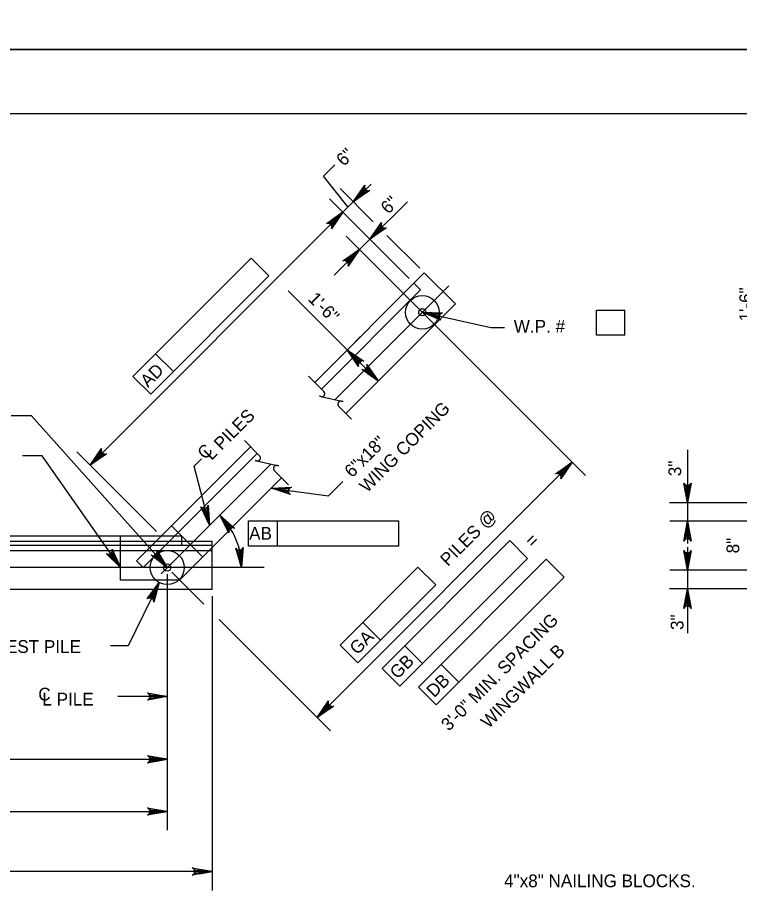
# Model space of a CAD drawing. Extents: x 638304 to 640306, y 296653 to 298435.
# Drawn here: x 638840 to 639009.6, y 297643.6 to 297849 of the extents above; entities that cross this region are included whole.
import ezdxf

# ---------------------------------------------------------------- set-up
doc = ezdxf.new("R2010")
doc.units = 0
for name, color, linetype in [('2', 7, 'Continuous'), ('Level 2', 7, 'Continuous'), ('Level 4', 7, 'Continuous'), ('Level 5', 7, 'Continuous'), ('PLT-BNDY', 7, 'Continuous')]:
    doc.layers.add(name, color=color, linetype=linetype)

msp = doc.modelspace()

# ---------------------------------------------------------------- linework, layer by layer
at = {"layer": '2'}
msp.add_line((638475.46, 297826.46), (639261.46, 297826.46), dxfattribs=at)
at = {"layer": 'Level 2'}
for p, q in [((638909.84, 297763.3), (638935.57, 297789.02)), ((638935.57, 297789.02), (638942.86, 297781.73)), ((638917.14, 297756), (638942.86, 297781.73)), ((638873.77, 297727.22), (638894.76, 297748.22)), ((638878.04, 297716.91), (638902.06, 297740.92)), ((638883.5, 297722.36), (638876.2, 297729.66)), ((638873.77, 297727.22), (638627.67, 297727.22)), ((638864.25, 297716.91), (638864.25, 297727.22)), ((638885.73, 297714.7), (638885.73, 297724.6)), ((638878.04, 297716.91), (638864.25, 297716.91)), ((638885.73, 297714.7), (638616.86, 297714.7))]:
    msp.add_line(p, q, dxfattribs=at)
msp.add_lwpolyline([(638864.25, 297719.86), (638845.84, 297746.05), (638841.24, 297746.05)], dxfattribs=at)
msp.add_lwpolyline([(638864.25, 297719.86), (638862.76, 297722.41), (638862.36, 297722.13)], close=True, dxfattribs=at)
at = {"layer": 'Level 4'}
for p, q in [((638911.41, 297761.73), (638934.7, 297785.02)), ((638933.14, 297786.59), (638934.7, 297785.02)), ((638869.53, 297719.86), (638896.33, 297746.65)), ((638873.77, 297727.22), (638867.97, 297721.42)), ((638878.65, 297727.22), (638873.77, 297727.22)), ((638878.65, 297725.01), (638878.65, 297727.22)), ((638616.86, 297726.08), (638885.73, 297726.08)), ((638885.73, 297724.6), (638885.73, 297726.08)), ((638885.73, 297725.01), (638616.86, 297725.01)), ((638616.86, 297723.87), (638885.73, 297723.87)), ((638869.53, 297719.86), (638867.97, 297721.42))]:
    msp.add_line(p, q, dxfattribs=at)
for points in [[(638935.1, 297779.76), (638951.19, 297776.21), (638954.41, 297776.21)], [(638875.2, 297719.86), (638843.29, 297755.47), (638838.53, 297755.47)], [(638899.66, 297738.52), (638913.04, 297736.69), (638916.4, 297740.04)]]:
    msp.add_lwpolyline(points, dxfattribs=at)
for points in [[(638935.1, 297779.76), (638937.93, 297778.88), (638938.04, 297779.36)], [(638899.66, 297738.52), (638902.54, 297737.88), (638902.61, 297738.36)], [(638875.2, 297719.86), (638873.42, 297722.22), (638873.05, 297721.89)]]:
    msp.add_lwpolyline(points, close=True, dxfattribs=at)
for centre, radius in [((638935.1, 297779.76), 3.93), ((638875.2, 297719.86), 4.01)]:
    msp.add_circle(centre, radius, dxfattribs=at)
at = {"layer": 'Level 5'}
for p, q in [((638911.91, 297811.73), (638914.59, 297814.41)), ((638917.68, 297804.47), (638911.91, 297811.73)), ((638918.9, 297805.69), (638923.06, 297809.86)), ((638923.58, 297801.01), (638915.77, 297808.82)), ((638932.05, 297787.67), (638913.34, 297806.39)), ((638914.03, 297800.83), (638918.9, 297805.69)), ((638922.81, 297796.92), (638931.6, 297805.7)), ((638857.1, 297743.9), (638916.46, 297803.26)), ((638914.38, 297801.18), (638912.3, 297799.09)), ((638932.05, 297787.67), (638919.68, 297800.04)), ((638917.25, 297797.61), (638946.87, 297767.99)), ((638934.48, 297790.1), (638926.79, 297797.8)), ((638922.81, 297796.91), (638920.38, 297794.48)), ((638920.38, 297794.48), (638914.36, 297788.46)), ((638867.14, 297764.71), (638894.93, 297792.49)), ((638894.93, 297792.49), (638899.09, 297788.32)), ((638871.31, 297760.54), (638899.09, 297788.32)), ((638917.48, 297770.93), (638903.59, 297784.82)), ((638914.57, 297759.23), (638941.33, 297785.98)), ((638976.04, 297780.27), (638982.62, 297780.27)), ((638976.04, 297774.37), (638976.04, 297780.27)), ((638982.62, 297774.37), (638982.62, 297780.27)), ((638982.62, 297774.37), (638976.04, 297774.37)), ((638918.08, 297771.53), (638920.6, 297774.06)), ((638924.77, 297763.64), (638917.48, 297770.93)), ((638872.48, 297770.04), (638876.64, 297765.88)), ((638925.37, 297764.24), (638927.9, 297766.76)), ((638946.87, 297767.99), (638973.43, 297741.43)), ((638867.14, 297764.71), (638871.31, 297760.54)), ((638908.4, 297764.74), (638911.99, 297761.16)), ((638915.41, 297757.73), (638918.46, 297754.68)), ((638893.31, 297749.67), (638896.89, 297746.08)), ((638872.69, 297728.31), (638853.98, 297747.02)), ((638997.36, 297747.49), (638997.36, 297730.72)), ((638873.75, 297718.4), (638899.5, 297744.15)), ((638881.49, 297743.61), (638883.22, 297745.34)), ((638885.14, 297729.79), (638881.49, 297743.61)), ((638910.41, 297684.65), (638970.31, 297744.55)), ((638900.32, 297742.66), (638903.71, 297739.26)), ((638872.69, 297728.31), (638860.32, 297740.68)), ((639032.53, 297735.04), (638993.12, 297735.04)), ((638894.26, 297730.8), (638929.49, 297730.8)), ((638894.26, 297724.9), (638894.26, 297730.8)), ((638901.09, 297724.9), (638901.09, 297730.8)), ((638929.49, 297730.8), (638929.49, 297724.9)), ((639059.87, 297730.72), (638993.2, 297730.72)), ((638997.36, 297729.69), (638997.36, 297725.53)), ((638925.64, 297696.17), (638955.65, 297726.18)), ((638955.65, 297726.18), (638959.82, 297722.01)), ((638929.49, 297724.9), (638894.26, 297724.9)), ((638997.36, 297724.61), (638997.36, 297724.22)), ((638997.36, 297724.39), (638997.36, 297714.89)), ((638929.81, 297692.01), (638959.82, 297722.01)), ((638934.2, 297691.79), (638964.21, 297721.8)), ((638964.21, 297721.8), (638968.38, 297717.63)), ((638897.93, 297719.86), (638605.59, 297719.86)), ((638915.77, 297701.65), (638934.08, 297719.96)), ((638934.08, 297719.96), (638938.25, 297715.79)), ((639049.8, 297719.21), (638993.2, 297719.21)), ((638997.36, 297719.21), (638997.36, 297704.46)), ((638875.2, 297718.32), (638875.2, 297658.18)), ((638876.29, 297718.77), (638883.79, 297711.27)), ((638938.37, 297687.63), (638968.38, 297717.63)), ((638873.32, 297716.32), (638866.06, 297701.45)), ((638919.94, 297697.48), (638938.25, 297715.79)), ((639032.53, 297714.89), (638993.12, 297714.89)), ((638885.73, 297713.16), (638885.73, 297644.06)), ((638887.4, 297707.66), (638913.53, 297681.53)), ((638921.11, 297706.99), (638925.28, 297702.82)), ((638866.06, 297701.45), (638861.87, 297701.45)), ((638915.77, 297701.65), (638919.94, 297697.48)), ((638930.98, 297701.51), (638935.15, 297697.34)), ((638939.54, 297697.13), (638943.7, 297692.96)), ((638925.64, 297696.17), (638929.81, 297692.01)), ((638934.2, 297691.79), (638938.37, 297687.63)), ((638875.2, 297689.57), (638863.61, 297689.57)), ((638626.05, 297674.84), (638875.2, 297674.84)), ((638754.75, 297662.6), (638875.2, 297662.6)), ((638885.73, 297648.48), (638616.86, 297648.48))]:
    msp.add_line(p, q, dxfattribs=at)
for points in [[(638918.9, 297805.69), (638921.57, 297809.6), (638921.49, 297809.17), (638921.58, 297808.82), (638921.76, 297808.56), (638922.02, 297808.38), (638922.37, 297808.29), (638922.8, 297808.36), (638918.9, 297805.69), (638922.37, 297808.29), (638922.02, 297808.38), (638918.9, 297805.69), (638921.76, 297808.56), (638921.58, 297808.82), (638918.9, 297805.69), (638921.49, 297809.17)], [(638916.46, 297803.26), (638913.79, 297799.35), (638913.87, 297799.78), (638913.78, 297800.13), (638913.6, 297800.39), (638913.34, 297800.57), (638912.99, 297800.66), (638912.56, 297800.59), (638916.46, 297803.26), (638912.99, 297800.66), (638913.34, 297800.57), (638916.46, 297803.26), (638913.6, 297800.39), (638913.78, 297800.13), (638916.46, 297803.26), (638913.87, 297799.78)], [(638922.81, 297796.92), (638925.48, 297800.82), (638925.41, 297800.39), (638925.5, 297800.04), (638925.68, 297799.78), (638925.94, 297799.6), (638926.29, 297799.51), (638926.72, 297799.59), (638922.81, 297796.92), (638926.29, 297799.51), (638925.94, 297799.6), (638922.81, 297796.92), (638925.68, 297799.78), (638925.5, 297800.04), (638922.81, 297796.92), (638925.41, 297800.39)], [(638920.38, 297794.48), (638917.71, 297790.58), (638917.78, 297791.01), (638917.69, 297791.36), (638917.51, 297791.62), (638917.25, 297791.8), (638916.9, 297791.89), (638916.47, 297791.81), (638920.38, 297794.48), (638916.9, 297791.89), (638917.25, 297791.8), (638920.38, 297794.48), (638917.51, 297791.62), (638917.69, 297791.36), (638920.38, 297794.48), (638917.78, 297791.01)], [(638935.1, 297779.76), (638939.83, 297779.61), (638939.43, 297779.44), (638939.18, 297779.18), (638939.06, 297778.89), (638939.05, 297778.57), (638939.16, 297778.23), (638939.46, 297777.9), (638935.1, 297779.76), (638939.16, 297778.23), (638939.05, 297778.57), (638935.1, 297779.76), (638939.06, 297778.89), (638939.18, 297779.18), (638935.1, 297779.76), (638939.43, 297779.44)], [(638917.48, 297770.93), (638921.38, 297768.26), (638920.96, 297768.34), (638920.6, 297768.25), (638920.34, 297768.07), (638920.16, 297767.81), (638920.07, 297767.46), (638920.15, 297767.03), (638917.48, 297770.93), (638920.07, 297767.46), (638920.16, 297767.81), (638917.48, 297770.93), (638920.34, 297768.07), (638920.6, 297768.25), (638917.48, 297770.93), (638920.96, 297768.34)], [(638924.77, 297763.64), (638920.87, 297766.31), (638921.29, 297766.23), (638921.65, 297766.32), (638921.91, 297766.5), (638922.09, 297766.76), (638922.18, 297767.11), (638922.1, 297767.54), (638924.77, 297763.64), (638922.18, 297767.11), (638922.09, 297766.76), (638924.77, 297763.64), (638921.91, 297766.5), (638921.65, 297766.32), (638924.77, 297763.64), (638921.29, 297766.23)], [(638911.3, 297759.97), (638910.96, 297760.05), (638916.49, 297758.79), (638916.12, 297758.87)], [(638857.1, 297743.9), (638859.77, 297747.8), (638859.7, 297747.37), (638859.79, 297747.02), (638859.97, 297746.76), (638860.23, 297746.58), (638860.58, 297746.49), (638861.01, 297746.57), (638857.1, 297743.9), (638860.58, 297746.49), (638860.23, 297746.58), (638857.1, 297743.9), (638859.97, 297746.76), (638859.79, 297747.02), (638857.1, 297743.9), (638859.7, 297747.37)], [(638896.21, 297744.9), (638895.87, 297744.98), (638901.4, 297743.72), (638901.03, 297743.8)], [(638970.31, 297744.55), (638967.64, 297740.65), (638967.71, 297741.08), (638967.62, 297741.43), (638967.44, 297741.69), (638967.18, 297741.87), (638966.83, 297741.96), (638966.4, 297741.88), (638970.31, 297744.55), (638966.83, 297741.96), (638967.18, 297741.87), (638970.31, 297744.55), (638967.44, 297741.69), (638967.62, 297741.43), (638970.31, 297744.55), (638967.71, 297741.08)], [(638997.36, 297735.04), (638996.49, 297739.69), (638996.74, 297739.33), (638997.05, 297739.15), (638997.36, 297739.1), (638997.67, 297739.15), (638997.98, 297739.33), (638998.23, 297739.69), (638997.36, 297735.04), (638997.98, 297739.33), (638997.67, 297739.15), (638997.36, 297735.04), (638997.36, 297739.1), (638997.05, 297739.15), (638997.36, 297735.04), (638996.74, 297739.33)], [(638899.66, 297738.52), (638904.38, 297738.75), (638903.99, 297738.56), (638903.77, 297738.27), (638903.67, 297737.97), (638903.68, 297737.65), (638903.83, 297737.32), (638904.15, 297737.03), (638899.66, 297738.52), (638903.83, 297737.32), (638903.68, 297737.65), (638899.66, 297738.52), (638903.67, 297737.97), (638903.77, 297738.27), (638899.66, 297738.52), (638903.99, 297738.56)], [(638885.14, 297729.79), (638883.11, 297734.07), (638883.44, 297733.78), (638883.79, 297733.68), (638884.1, 297733.71), (638884.39, 297733.84), (638884.64, 297734.1), (638884.79, 297734.51), (638885.14, 297729.79), (638884.64, 297734.1), (638884.39, 297733.84), (638885.14, 297729.79), (638884.1, 297733.71), (638883.79, 297733.68), (638885.14, 297729.79), (638883.44, 297733.78)], [(638887.53, 297732.18), (638891.06, 297729.03), (638890.65, 297729.16), (638890.29, 297729.12), (638890.01, 297728.97), (638889.79, 297728.74), (638889.66, 297728.4), (638889.68, 297727.97), (638887.53, 297732.18), (638889.66, 297728.4), (638889.79, 297728.74), (638887.53, 297732.18), (638890.01, 297728.97), (638890.29, 297729.12), (638887.53, 297732.18), (638890.65, 297729.16)], [(638997.36, 297730.72), (638998.23, 297726.07), (638997.98, 297726.43), (638997.67, 297726.62), (638997.36, 297726.67), (638997.05, 297726.62), (638996.74, 297726.43), (638996.49, 297726.07), (638997.36, 297730.72), (638996.74, 297726.43), (638997.05, 297726.62), (638997.36, 297730.72), (638997.36, 297726.67), (638997.67, 297726.62), (638997.36, 297730.72), (638997.98, 297726.43)], [(638864.25, 297719.86), (638860.87, 297723.16), (638861.27, 297723.01), (638861.64, 297723.04), (638861.92, 297723.17), (638862.15, 297723.4), (638862.29, 297723.73), (638862.29, 297724.16), (638864.25, 297719.86), (638862.29, 297723.73), (638862.15, 297723.4), (638864.25, 297719.86), (638861.92, 297723.17), (638861.64, 297723.04), (638864.25, 297719.86), (638861.27, 297723.01)], [(638875.2, 297719.86), (638871.45, 297722.74), (638871.87, 297722.64), (638872.23, 297722.71), (638872.5, 297722.88), (638872.69, 297723.13), (638872.8, 297723.47), (638872.75, 297723.9), (638875.2, 297719.86), (638872.8, 297723.47), (638872.69, 297723.13), (638875.2, 297719.86), (638872.5, 297722.88), (638872.23, 297722.71), (638875.2, 297719.86), (638871.87, 297722.64)], [(638892.66, 297719.87), (638891.28, 297724.39), (638891.57, 297724.06), (638891.9, 297723.91), (638892.21, 297723.9), (638892.52, 297723.98), (638892.81, 297724.2), (638893.02, 297724.58), (638892.66, 297719.87), (638892.81, 297724.2), (638892.52, 297723.98), (638892.66, 297719.87), (638892.21, 297723.9), (638891.9, 297723.91), (638892.66, 297719.87), (638891.57, 297724.06)], [(638997.36, 297719.21), (638996.49, 297723.86), (638996.74, 297723.5), (638997.05, 297723.32), (638997.36, 297723.27), (638997.67, 297723.32), (638997.98, 297723.5), (638998.23, 297723.86), (638997.36, 297719.21), (638997.98, 297723.5), (638997.67, 297723.32), (638997.36, 297719.21), (638997.36, 297723.27), (638997.05, 297723.32), (638997.36, 297719.21), (638996.74, 297723.5)], [(638873.32, 297716.32), (638872.06, 297711.75), (638872, 297712.18), (638871.8, 297712.49), (638871.54, 297712.67), (638871.24, 297712.76), (638870.88, 297712.73), (638870.5, 297712.52), (638873.32, 297716.32), (638870.88, 297712.73), (638871.24, 297712.76), (638873.32, 297716.32), (638871.54, 297712.67), (638871.8, 297712.49), (638873.32, 297716.32), (638872, 297712.18)], [(638997.36, 297714.89), (638998.23, 297710.24), (638997.98, 297710.6), (638997.67, 297710.79), (638997.36, 297710.84), (638997.05, 297710.79), (638996.74, 297710.6), (638996.49, 297710.24), (638997.36, 297714.89), (638996.74, 297710.6), (638997.05, 297710.79), (638997.36, 297714.89), (638997.36, 297710.84), (638997.67, 297710.79), (638997.36, 297714.89), (638997.98, 297710.6)], [(638875.2, 297689.57), (638870.55, 297688.69), (638870.91, 297688.94), (638871.09, 297689.25), (638871.15, 297689.57), (638871.09, 297689.88), (638870.91, 297690.19), (638870.55, 297690.44), (638875.2, 297689.57), (638870.91, 297690.19), (638871.09, 297689.88), (638875.2, 297689.57), (638871.15, 297689.57), (638871.09, 297689.25), (638875.2, 297689.57), (638870.91, 297688.94)], [(638910.41, 297684.65), (638913.08, 297688.56), (638913, 297688.13), (638913.09, 297687.78), (638913.27, 297687.52), (638913.53, 297687.34), (638913.88, 297687.25), (638914.31, 297687.33), (638910.41, 297684.65), (638913.88, 297687.25), (638913.53, 297687.34), (638910.41, 297684.65), (638913.27, 297687.52), (638913.09, 297687.78), (638910.41, 297684.65), (638913, 297688.13)], [(638875.2, 297674.84), (638870.55, 297673.97), (638870.91, 297674.21), (638871.09, 297674.53), (638871.15, 297674.84), (638871.09, 297675.15), (638870.91, 297675.46), (638870.55, 297675.71), (638875.2, 297674.84), (638870.91, 297675.46), (638871.09, 297675.15), (638875.2, 297674.84), (638871.15, 297674.84), (638871.09, 297674.53), (638875.2, 297674.84), (638870.91, 297674.21)], [(638875.2, 297662.6), (638870.55, 297661.73), (638870.91, 297661.98), (638871.09, 297662.29), (638871.15, 297662.6), (638871.09, 297662.91), (638870.91, 297663.23), (638870.55, 297663.47), (638875.2, 297662.6), (638870.91, 297663.23), (638871.09, 297662.91), (638875.2, 297662.6), (638871.15, 297662.6), (638871.09, 297662.29), (638875.2, 297662.6), (638870.91, 297661.98)], [(638885.73, 297648.48), (638881.08, 297647.61), (638881.44, 297647.86), (638881.62, 297648.17), (638881.68, 297648.48), (638881.62, 297648.8), (638881.44, 297649.11), (638881.08, 297649.35), (638885.73, 297648.48), (638881.44, 297649.11), (638881.62, 297648.8), (638885.73, 297648.48), (638881.68, 297648.48), (638881.62, 297648.17), (638885.73, 297648.48), (638881.44, 297647.86)]]:
    msp.add_lwpolyline(points, dxfattribs=at)
for points in [[(638920.63, 297808.12), (638921.33, 297807.43), (638918.9, 297805.69)], [(638914.03, 297801.52), (638914.73, 297800.83), (638916.46, 297803.26)], [(638924.54, 297799.35), (638925.24, 297798.65), (638922.81, 297796.91)], [(638917.95, 297792.75), (638918.64, 297792.05), (638920.38, 297794.48)], [(638919.91, 297769.19), (638919.22, 297768.5), (638917.48, 297770.93)], [(638923.04, 297766.07), (638922.34, 297765.37), (638924.77, 297763.64)], [(638858.84, 297746.33), (638859.53, 297745.63), (638857.1, 297743.89)], [(638967.88, 297742.82), (638968.57, 297742.12), (638970.31, 297744.55)], [(638884.86, 297732.77), (638883.91, 297732.51), (638885.14, 297729.79)], [(638872.25, 297689.07), (638872.25, 297690.06), (638875.2, 297689.57)], [(638912.14, 297687.08), (638912.84, 297686.39), (638910.41, 297684.65)], [(638872.25, 297675.33), (638872.25, 297674.34), (638875.2, 297674.84)], [(638872.25, 297663.09), (638872.25, 297662.11), (638875.2, 297662.6)], [(638882.79, 297648.97), (638882.79, 297647.99), (638885.73, 297648.48)]]:
    msp.add_lwpolyline(points, close=True, dxfattribs=at)
for centre in [(638935.1, 297779.76), (638875.2, 297719.86)]:
    msp.add_circle(centre, 0.849, dxfattribs=at)
for centre, radius, start, end in [((638911.48, 297760.66), 0.709, 255, 45), ((638915.96, 297758.18), 0.709, 77.1328, 219.6714), ((638896.39, 297745.58), 0.709, 255, 45), ((638900.87, 297743.11), 0.709, 77.1328, 219.6714), ((638875.37, 297719.86), 17.29, 0.0009, 45.394)]:
    msp.add_arc(centre, radius, start, end, dxfattribs=at)
at = {"layer": 'PLT-BNDY'}
for points in [[(638435.46, 298435.46), (639276.46, 298435.46), (639276.46, 297841.46), (638435.46, 297841.46)], [(638435.46, 297841.46), (639276.46, 297841.46), (639276.46, 297247.46), (638435.46, 297247.46)]]:
    msp.add_lwpolyline(points, close=True, dxfattribs=at)

# ---------------------------------------------------------------- texts
at = {"layer": 'Level 5'}
for s, height, rotation, p in [('6"', 3, 45, (638916.69, 297813.89)), ('6"', 3, 45, (638927.13, 297802.65)), ('1\'-6"', 3, 90, (639012.54, 297777.63)), ('1\'-6"', 3, 315, (638908.11, 297782.71)), ('AD', 3, 45, (638870.68, 297761.96)), ('WING COPING', 3.0001, 45, (638922.14, 297737.25)), ('L PILES', 3, 45, (638885.6, 297744.84)), ('6"x18"', 3, 45, (638918.61, 297740.78)), ('C', 3, 45, (638884.08, 297745.01)), ('3"', 3, 90, (638995.9, 297741.29)), ('PILES @', 3, 44.9382, (638941.1, 297720.01)), ('=', 3, 44.9382, (638961.04, 297724.36)), ('8"', 3, 90, (639009.53, 297723.18)), ('3\'-0" MIN. SPACING', 3.0001, 45, (638941.31, 297681.31)), ('3"', 3, 90, (638996.43, 297705.2)), ('GA', 3, 44.9382, (638919.84, 297699.22)), ('WINGWALL B', 3, 45, (638950.67, 297681.93)), ('GB', 3, 44.9382, (638929.27, 297693.51)), ('DB', 3, 44.9382, (638937.86, 297689.16))]:
    msp.add_text(s, height=height, rotation=rotation, dxfattribs=at).set_placement(p)
for s, height, p in [('W.P. #', 3, (638956.58, 297774.97)), ('AB', 3, (638894.43, 297726.38)), ('TEST PILE', 3, (638834.87, 297699.81)), ('C', 3, (638844.92, 297688.64)), ('L PILE', 3, (638845.89, 297687.46)), ('4"x8" NAILING BLOCKS.  ', 3.0001, (638954.31, 297644.82))]:
    msp.add_text(s, height=height, dxfattribs=at).set_placement(p)

doc.saveas('drawing.dxf')
